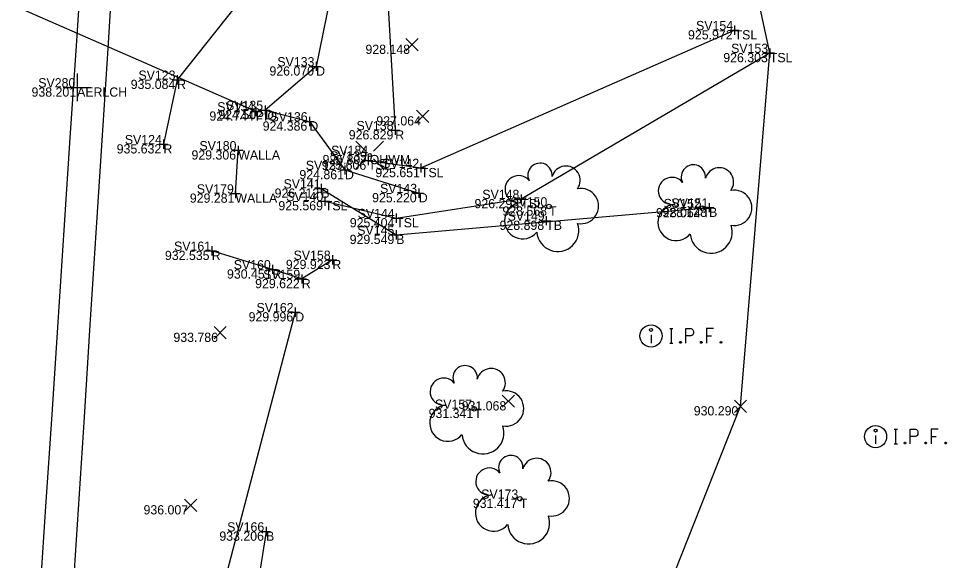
# Model space of a CAD drawing. Extents: x 1988835 to 1989144, y 657973 to 659339.
# Drawn here: x 1988993.8 to 1989094.4, y 658616.1 to 658674.7 of the extents above; entities that cross this region are included whole.
import ezdxf

# ---------------------------------------------------------------- set-up
doc = ezdxf.new("R2010")
doc.units = 0
for name, color, linetype in [('BR_X_SV_Abut', 7, 'Continuous'), ('BR_X_SV_Abut_Text', 7, 'Continuous'), ('DR_X_Culvert', 7, 'Continuous'), ('DR_X_Ditch', 7, 'Continuous'), ('DR_X_Elev_Flow', 7, 'Continuous'), ('DR_X_Erosion_Control', 7, 'Continuous'), ('DT_X_Terrain_Boundary', 7, 'Continuous'), ('PV_X_EOP', 7, 'Continuous'), ('PV_X_Shoulder_Aggregate', 7, 'Continuous'), ('SV_X_Break_Lines', 7, 'Continuous'), ('SV_X_Control_Cells_Found', 7, 'Continuous'), ('SV_X_LiDAR_Check_Spots', 7, 'Continuous'), ('SV_X_Mon_Cells_Found', 7, 'Continuous'), ('SV_X_Random_Point', 7, 'Continuous'), ('SV_X_Shot_Marker', 7, 'Continuous'), ('SV_X_Text_Comment', 7, 'Continuous'), ('SV_X_Toe_of_Slope', 7, 'Continuous'), ('SV_X_Top_of_Bank', 7, 'Continuous'), ('UT_X_Telecom', 7, 'Continuous'), ('UT_X_Telecom_Cells', 7, 'Continuous'), ('VG_X_Cells', 7, 'Continuous')]:
    doc.layers.add(name, color=color, linetype=linetype)

msp = doc.modelspace()

# ---------------------------------------------------------------- linework, layer by layer
at = {"layer": 'BR_X_SV_Abut'}
msp.add_lwpolyline([(1989017.3, 658655.79), (1989017.61, 658660.47)], dxfattribs=at)
at = {"layer": 'DR_X_Culvert'}
msp.add_line((1989019.51, 658664.68), (1988958.48, 658691.4), dxfattribs=at)
at = {"layer": 'DR_X_Ditch'}
for points in [[(1989027.55, 658676.83), (1989026.05, 658669.56), (1989020.51, 658664.83), (1989025.32, 658663.6), (1989029.18, 658658.34), (1989037.18, 658655.84)], [(1989023.79, 658642.94), (1989012.7, 658600.75), (1989009.34, 658575.2), (1989005.48, 658554.05)]]:
    msp.add_lwpolyline(points, dxfattribs=at)
at = {"layer": 'DR_X_Elev_Flow'}
for p, q in [((1989019.51, 658665.18), (1989019.51, 658664.18)), ((1989019.01, 658664.68), (1989020.01, 658664.68)), ((1989019.51, 658664.68), (1989019.51, 658664.68))]:
    msp.add_line(p, q, dxfattribs=at)
at = {"layer": 'DR_X_Erosion_Control'}
for points in [[(1989026.58, 658683.91), (1989017.28, 658675.99), (1989010.98, 658668.11), (1989009.49, 658661.13)], [(1989033.84, 658676.66), (1989034.63, 658662.65)], [(1989027.81, 658648.61), (1989024.5, 658646.54), (1989021.33, 658647.58), (1989014.73, 658649.59)]]:
    msp.add_lwpolyline(points, dxfattribs=at)
at = {"layer": 'DT_X_Terrain_Boundary'}
msp.add_lwpolyline([(1988964.62, 658494.73), (1988978, 658493.13), (1988991.98, 658491.88), (1988996.56, 658563.26), (1989005.48, 658554.05), (1989016.29, 658553.87), (1989055.69, 658591.48), (1989072.05, 658632.76), (1989075.24, 658671.01), (1989070.71, 658691.89), (1989069.57, 658706.91), (1989055.31, 658717.34), (1989045.38, 658731.75), (1989037.8, 658764.08), (1989044.5, 658795.25), (1989034.59, 658795.83), (1989024.05, 658796.33), (1989020.1, 658798.63), (1989011.65, 658798.86), (1989014.02, 658836.36)], dxfattribs=at)
at = {"layer": 'PV_X_EOP'}
msp.add_lwpolyline([(1988996.1, 658611.92), (1988996.76, 658621.89), (1988997.42, 658631.87), (1988998.08, 658641.85), (1988998.74, 658651.83), (1988999.4, 658661.81), (1989000.06, 658671.78), (1989000.73, 658681.76), (1989001.39, 658691.74), (1989002.05, 658701.72), (1989002.71, 658711.7), (1989003.37, 658721.68), (1989004.03, 658731.65), (1989004.69, 658741.63), (1989005.35, 658751.61), (1989006.01, 658761.59), (1989006.67, 658771.57), (1989007.33, 658781.54), (1989007.99, 658791.52), (1989008.65, 658801.5), (1989009.31, 658811.48), (1989009.97, 658821.46), (1989010.63, 658831.43), (1989011.29, 658841.41)], dxfattribs=at)
at = {"layer": 'PV_X_Shoulder_Aggregate'}
msp.add_lwpolyline([(1988999.65, 658611.63), (1989000.29, 658621.61), (1989000.93, 658631.59), (1989001.57, 658641.57), (1989002.21, 658651.55), (1989002.85, 658661.53), (1989003.49, 658671.51), (1989004.13, 658681.49), (1989004.77, 658691.47), (1989005.41, 658701.45), (1989006.05, 658711.43), (1989006.69, 658721.41), (1989007.33, 658731.39), (1989007.96, 658741.37), (1989008.6, 658751.35), (1989009.24, 658761.33), (1989009.88, 658771.31), (1989010.52, 658781.29), (1989011.16, 658791.27), (1989011.8, 658801.25), (1989012.44, 658811.22), (1989013.08, 658821.2), (1989013.72, 658831.18), (1989013.76, 658831.87)], dxfattribs=at)
at = {"layer": 'SV_X_Break_Lines'}
for points in [[(1989026.61, 658656.34), (1989034.73, 658651.32), (1989068.65, 658654.26)], [(1989020.62, 658619.19), (1989017.63, 658600.41), (1989016.29, 658553.87)]]:
    msp.add_lwpolyline(points, dxfattribs=at)
at = {"layer": 'SV_X_Control_Cells_Found'}
for p, q in [((1989030.35, 658661.47), (1989031.44, 658660.38)), ((1989032.27, 658660.38), (1989033.36, 658661.47)), ((1989030.35, 658658.45), (1989031.44, 658659.55)), ((1989032.27, 658659.55), (1989033.36, 658658.45))]:
    msp.add_line(p, q, dxfattribs=at)
msp.add_circle((1989031.86, 658659.97), 0.17, dxfattribs=at)
at = {"layer": 'SV_X_LiDAR_Check_Spots'}
for p, q in [((1989000.14, 658668.78), (1989000.14, 658665.78)), ((1988998.64, 658667.28), (1989001.64, 658667.28)), ((1989000.14, 658667.28), (1989000.14, 658667.28))]:
    msp.add_line(p, q, dxfattribs=at)
at = {"layer": 'SV_X_Mon_Cells_Found'}
for p, q in [((1989062.36, 658640.49), (1989062.36, 658639.6)), ((1989086.7, 658629.59), (1989086.7, 658628.7))]:
    msp.add_line(p, q, dxfattribs=at)
for points in [[(1989064.39, 658641.17), (1989064.74, 658641.17)], [(1989064.57, 658639.57), (1989064.57, 658641.17)], [(1989066.13, 658639.57), (1989066.13, 658641.17), (1989066.66, 658641.17), (1989066.72, 658641.16), (1989066.79, 658641.13), (1989066.83, 658641.11), (1989066.86, 658641.08), (1989066.9, 658641.02), (1989066.94, 658640.96), (1989066.96, 658640.86), (1989066.96, 658640.7), (1989066.95, 658640.65), (1989066.93, 658640.58), (1989066.88, 658640.49), (1989066.84, 658640.45), (1989066.8, 658640.43), (1989066.75, 658640.4), (1989066.66, 658640.39), (1989066.13, 658640.39)], [(1989069.14, 658641.17), (1989068.38, 658641.17), (1989068.38, 658639.57)], [(1989064.39, 658639.57), (1989064.74, 658639.57)], [(1989065.53, 658639.78), (1989065.58, 658639.78), (1989065.61, 658639.76), (1989065.65, 658639.71), (1989065.65, 658639.65), (1989065.61, 658639.6), (1989065.58, 658639.57), (1989065.53, 658639.57), (1989065.49, 658639.6), (1989065.46, 658639.65), (1989065.46, 658639.71), (1989065.49, 658639.76), (1989065.53, 658639.78)], [(1989067.77, 658639.78), (1989067.83, 658639.78), (1989067.86, 658639.76), (1989067.9, 658639.71), (1989067.9, 658639.65), (1989067.86, 658639.6), (1989067.83, 658639.57), (1989067.77, 658639.57), (1989067.74, 658639.6), (1989067.71, 658639.65), (1989067.71, 658639.71), (1989067.74, 658639.76), (1989067.77, 658639.78)], [(1989068.38, 658640.39), (1989068.92, 658640.39)], [(1989069.92, 658639.78), (1989069.98, 658639.78), (1989070.01, 658639.76), (1989070.05, 658639.71), (1989070.05, 658639.65), (1989070.01, 658639.6), (1989069.98, 658639.57), (1989069.92, 658639.57), (1989069.89, 658639.6), (1989069.86, 658639.65), (1989069.86, 658639.71), (1989069.89, 658639.76), (1989069.92, 658639.78)], [(1989088.73, 658630.27), (1989089.08, 658630.27)], [(1989088.91, 658628.67), (1989088.91, 658630.27)], [(1989090.47, 658628.67), (1989090.47, 658630.27), (1989091, 658630.27), (1989091.06, 658630.26), (1989091.13, 658630.23), (1989091.17, 658630.21), (1989091.2, 658630.18), (1989091.24, 658630.12), (1989091.28, 658630.06), (1989091.3, 658629.96), (1989091.3, 658629.8), (1989091.29, 658629.75), (1989091.27, 658629.68), (1989091.22, 658629.59), (1989091.18, 658629.55), (1989091.14, 658629.53), (1989091.09, 658629.5), (1989091, 658629.49), (1989090.47, 658629.49)], [(1989093.48, 658630.27), (1989092.72, 658630.27), (1989092.72, 658628.67)], [(1989088.73, 658628.67), (1989089.08, 658628.67)], [(1989089.87, 658628.88), (1989089.92, 658628.88), (1989089.95, 658628.86), (1989089.99, 658628.81), (1989089.99, 658628.75), (1989089.95, 658628.7), (1989089.92, 658628.67), (1989089.87, 658628.67), (1989089.83, 658628.7), (1989089.8, 658628.75), (1989089.8, 658628.81), (1989089.83, 658628.86), (1989089.87, 658628.88)], [(1989092.11, 658628.88), (1989092.17, 658628.88), (1989092.2, 658628.86), (1989092.24, 658628.81), (1989092.24, 658628.75), (1989092.2, 658628.7), (1989092.17, 658628.67), (1989092.11, 658628.67), (1989092.08, 658628.7), (1989092.05, 658628.75), (1989092.05, 658628.81), (1989092.08, 658628.86), (1989092.11, 658628.88)], [(1989092.72, 658629.49), (1989093.26, 658629.49)], [(1989094.26, 658628.88), (1989094.32, 658628.88), (1989094.35, 658628.86), (1989094.39, 658628.81), (1989094.39, 658628.75), (1989094.35, 658628.7), (1989094.32, 658628.67), (1989094.26, 658628.67), (1989094.23, 658628.7), (1989094.2, 658628.75), (1989094.2, 658628.81), (1989094.23, 658628.86), (1989094.26, 658628.88)]]:
    msp.add_lwpolyline(points, dxfattribs=at)
for centre, radius in [((1989062.36, 658640.37), 1.2), ((1989062.36, 658641.02), 0.16), ((1989086.7, 658629.47), 1.2), ((1989086.7, 658630.12), 0.16)]:
    msp.add_circle(centre, radius, dxfattribs=at)
at = {"layer": 'SV_X_Random_Point'}
for p, q in [((1989035.79, 658671.24), (1989037.12, 658672.58)), ((1989035.79, 658672.58), (1989037.12, 658671.24)), ((1989036.94, 658663.49), (1989038.27, 658664.83)), ((1989036.94, 658664.83), (1989038.27, 658663.49)), ((1989014.98, 658640.05), (1989016.31, 658641.39)), ((1989014.98, 658641.39), (1989016.31, 658640.05)), ((1989046.22, 658632.64), (1989047.56, 658633.97)), ((1989046.22, 658633.97), (1989047.56, 658632.64)), ((1989071.39, 658632.09), (1989072.72, 658633.43)), ((1989071.39, 658633.43), (1989072.72, 658632.09)), ((1989011.78, 658621.37), (1989013.11, 658622.71)), ((1989011.78, 658622.71), (1989013.11, 658621.37))]:
    msp.add_line(p, q, dxfattribs=at)
at = {"layer": 'SV_X_Shot_Marker'}
for p, q in [((1989071.42, 658673.98), (1989071.42, 658672.98)), ((1989070.92, 658673.48), (1989071.92, 658673.48)), ((1989071.42, 658673.48), (1989071.42, 658673.48)), ((1989074.74, 658671.01), (1989075.74, 658671.01)), ((1989075.24, 658671.51), (1989075.24, 658670.51)), ((1989075.24, 658671.01), (1989075.24, 658671.01)), ((1989026.05, 658670.06), (1989026.05, 658669.06)), ((1989025.55, 658669.56), (1989026.55, 658669.56)), ((1989026.05, 658669.56), (1989026.05, 658669.56)), ((1989010.48, 658668.11), (1989011.48, 658668.11)), ((1989010.98, 658668.61), (1989010.98, 658667.61)), ((1989010.98, 658668.11), (1989010.98, 658668.11)), ((1989020.01, 658664.83), (1989021.01, 658664.83)), ((1989020.51, 658665.33), (1989020.51, 658664.33)), ((1989020.51, 658664.83), (1989020.51, 658664.83)), ((1989025.32, 658664.1), (1989025.32, 658663.1)), ((1989024.82, 658663.6), (1989025.82, 658663.6)), ((1989025.32, 658663.6), (1989025.32, 658663.6)), ((1989034.63, 658663.15), (1989034.63, 658662.15)), ((1989034.13, 658662.65), (1989035.13, 658662.65)), ((1989034.63, 658662.65), (1989034.63, 658662.65)), ((1989008.99, 658661.13), (1989009.99, 658661.13)), ((1989009.49, 658661.63), (1989009.49, 658660.63)), ((1989009.49, 658661.13), (1989009.49, 658661.13)), ((1989017.61, 658660.97), (1989017.61, 658659.97)), ((1989017.11, 658660.47), (1989018.11, 658660.47)), ((1989017.61, 658660.47), (1989017.61, 658660.47)), ((1989031.71, 658659.86), (1989031.71, 658658.86)), ((1989029.18, 658658.84), (1989029.18, 658657.84)), ((1989031.21, 658659.36), (1989032.21, 658659.36)), ((1989031.71, 658659.36), (1989031.71, 658659.36)), ((1989037.41, 658659.06), (1989037.41, 658658.06)), ((1989028.68, 658658.34), (1989029.68, 658658.34)), ((1989029.18, 658658.34), (1989029.18, 658658.34)), ((1989036.91, 658658.56), (1989037.91, 658658.56)), ((1989037.41, 658658.56), (1989037.41, 658658.56)), ((1989026.61, 658656.84), (1989026.61, 658655.84)), ((1989016.8, 658655.79), (1989017.8, 658655.79)), ((1989017.3, 658656.29), (1989017.3, 658655.29)), ((1989017.3, 658655.79), (1989017.3, 658655.79)), ((1989026.11, 658656.34), (1989027.11, 658656.34)), ((1989026.61, 658656.34), (1989026.61, 658656.34)), ((1989036.68, 658655.84), (1989037.68, 658655.84)), ((1989037.18, 658656.34), (1989037.18, 658655.34)), ((1989037.18, 658655.84), (1989037.18, 658655.84)), ((1989048.27, 658655.7), (1989048.27, 658654.7)), ((1989026.5, 658654.97), (1989027.5, 658654.97)), ((1989027, 658655.47), (1989027, 658654.47)), ((1989027, 658654.97), (1989027, 658654.97)), ((1989047.77, 658655.2), (1989048.77, 658655.2)), ((1989048.27, 658655.2), (1989048.27, 658655.2)), ((1989068.65, 658654.76), (1989068.65, 658653.76)), ((1989068.15, 658654.26), (1989069.15, 658654.26)), ((1989068.65, 658654.26), (1989068.65, 658654.26)), ((1989034.23, 658653.13), (1989035.23, 658653.13)), ((1989034.73, 658653.63), (1989034.73, 658652.63)), ((1989034.73, 658653.13), (1989034.73, 658653.13)), ((1989050.5, 658652.85), (1989051.5, 658652.85)), ((1989051, 658653.35), (1989051, 658652.35)), ((1989051, 658652.85), (1989051, 658652.85)), ((1989034.73, 658651.82), (1989034.73, 658650.82)), ((1989034.23, 658651.32), (1989035.23, 658651.32)), ((1989034.73, 658651.32), (1989034.73, 658651.32)), ((1989014.73, 658650.09), (1989014.73, 658649.09)), ((1989014.23, 658649.59), (1989015.23, 658649.59)), ((1989014.73, 658649.59), (1989014.73, 658649.59)), ((1989027.81, 658649.11), (1989027.81, 658648.11)), ((1989021.33, 658648.08), (1989021.33, 658647.08)), ((1989027.31, 658648.61), (1989028.31, 658648.61)), ((1989027.81, 658648.61), (1989027.81, 658648.61)), ((1989020.83, 658647.58), (1989021.83, 658647.58)), ((1989021.33, 658647.58), (1989021.33, 658647.58)), ((1989024.5, 658647.04), (1989024.5, 658646.04)), ((1989024, 658646.54), (1989025, 658646.54)), ((1989024.5, 658646.54), (1989024.5, 658646.54)), ((1989023.29, 658642.94), (1989024.29, 658642.94)), ((1989023.79, 658643.44), (1989023.79, 658642.44)), ((1989023.79, 658642.94), (1989023.79, 658642.94)), ((1989020.62, 658619.69), (1989020.62, 658618.69)), ((1989020.12, 658619.19), (1989021.12, 658619.19)), ((1989020.62, 658619.19), (1989020.62, 658619.19))]:
    msp.add_line(p, q, dxfattribs=at)
at = {"layer": 'SV_X_Toe_of_Slope'}
for points in [[(1989031.71, 658659.36), (1989037.41, 658658.56), (1989071.42, 658673.48)], [(1989027, 658654.97), (1989034.73, 658653.13), (1989048.27, 658655.2), (1989075.24, 658671.01)]]:
    msp.add_lwpolyline(points, dxfattribs=at)
at = {"layer": 'SV_X_Top_of_Bank'}
msp.add_lwpolyline([(1989051, 658652.85), (1989051, 658652.85)], dxfattribs=at)
at = {"layer": 'VG_X_Cells'}
for centre in [(1989051.3, 658654.39), (1989067.93, 658654.21), (1989043.19, 658632.48), (1989048.14, 658622.74)]:
    msp.add_circle(centre, 0.24, dxfattribs=at)
for centre, radius, start, end in [((1989050.32, 658657.76), 1.32, 354.0047, 205.9741), ((1989053.13, 658657.22), 1.55, 323.83, 165.0376), ((1989066.95, 658657.58), 1.32, 354.0047, 205.9741), ((1989048, 658656.26), 1.47, 39.0625, 279.5412), ((1989069.76, 658657.04), 1.55, 323.83, 165.0376), ((1989064.62, 658656.07), 1.47, 39.0625, 279.5412), ((1989054.76, 658654.43), 1.91, 259.1453, 101.4596), ((1989071.39, 658654.24), 1.91, 259.1453, 101.4596), ((1989048.45, 658652.85), 1.97, 96.1722, 320.5737), ((1989065.08, 658652.66), 1.97, 96.1722, 320.5737), ((1989052.25, 658651.79), 2.28, 184.9476, 19.4572), ((1989068.88, 658651.6), 2.28, 184.9476, 19.4572), ((1989042.21, 658635.84), 1.32, 354.0047, 205.9741), ((1989045.02, 658635.3), 1.55, 323.83, 165.0376), ((1989039.88, 658634.34), 1.47, 39.0625, 279.5412), ((1989046.65, 658632.51), 1.91, 259.1453, 101.4596), ((1989040.34, 658630.93), 1.97, 96.1722, 320.5737), ((1989044.14, 658629.87), 2.28, 184.9476, 19.4572), ((1989047.16, 658626.11), 1.32, 354.0047, 205.9741), ((1989049.97, 658625.57), 1.55, 323.83, 165.0376), ((1989044.83, 658624.6), 1.47, 39.0625, 279.5412), ((1989051.6, 658622.77), 1.91, 259.1453, 101.4596), ((1989045.29, 658621.19), 1.97, 96.1722, 320.5737), ((1989049.09, 658620.13), 2.28, 184.9476, 19.4572)]:
    msp.add_arc(centre, radius, start, end, dxfattribs=at)

# ---------------------------------------------------------------- texts
at = {"layer": 'BR_X_SV_Abut_Text'}
for s, p in [('SV180', (1989013.4, 658660.47)), ('929.306', (1989012.54, 658659.47)), ('WALLA', (1989017.61, 658659.47)), ('SV179', (1989013.12, 658655.79)), ('929.281', (1989012.36, 658654.79)), ('WALLA', (1989017.3, 658654.79))]:
    msp.add_text(s, height=1, dxfattribs=at).set_placement(p)
at = {"layer": 'SV_X_Text_Comment'}
for s, p in [('SV154', (1989067.24, 658673.48)), ('SV153', (1989071.04, 658671.01)), ('SV133', (1989021.85, 658669.56)), ('SV123', (1989006.79, 658668.11)), ('SV280', (1988995.93, 658667.28)), ('SV135', (1989016.29, 658664.83)), ('SV134', (1989015.33, 658664.68)), ('SV136', (1989021.11, 658663.6)), ('SV138', (1989030.43, 658662.65)), ('SV124', (1989005.31, 658661.13)), ('SV184', (1989027.68, 658659.97)), ('SV139', (1989027.53, 658659.36)), ('SV137', (1989024.93, 658658.34)), ('SV142', (1989033.21, 658658.56)), ('SV141', (1989022.52, 658656.34)), ('SV143', (1989032.98, 658655.84)), ('SV140', (1989022.8, 658654.97)), ('SV148', (1989044.07, 658655.2)), ('SV150', (1989047.1, 658654.39)), ('SV152', (1989063.73, 658654.21)), ('SV151', (1989064.56, 658654.26)), ('SV144', (1989030.55, 658653.13)), ('SV149', (1989046.81, 658652.85)), ('SV145', (1989030.51, 658651.32)), ('SV161', (1989010.65, 658649.59)), ('SV158', (1989023.61, 658648.61)), ('SV160', (1989017.12, 658647.58)), ('SV159', (1989020.31, 658646.54)), ('SV162', (1989019.59, 658642.94)), ('SV157', (1989038.94, 658632.48)), ('SV173', (1989043.95, 658622.74)), ('SV166', (1989016.41, 658619.19))]:
    msp.add_text(s, height=1, dxfattribs=at).set_placement(p)
at = {"layer": 'UT_X_Telecom'}
for s, p in [('TSL', (1989071.42, 658672.48)), ('TSL', (1989075.24, 658670.01)), ('D', (1989026.05, 658668.56)), ('R', (1989010.98, 658667.11)), ('AERLCH', (1989000.14, 658666.28)), ('D', (1989020.51, 658663.83)), ('PIO', (1989019.51, 658663.68)), ('D', (1989025.32, 658662.6)), ('R', (1989034.63, 658661.65)), ('R', (1989009.49, 658660.13)), ('OHWM', (1989031.86, 658658.97)), ('TSL', (1989031.71, 658658.36)), ('D', (1989029.18, 658657.34)), ('TSL', (1989037.41, 658657.56)), ('B', (1989026.61, 658655.34)), ('D', (1989037.18, 658654.84)), ('TSL', (1989027, 658653.97)), ('TSL', (1989048.27, 658654.2)), ('T', (1989051.3, 658653.39)), ('T', (1989067.93, 658653.21)), ('B', (1989068.65, 658653.26)), ('TSL', (1989034.73, 658652.13)), ('TB', (1989051, 658651.85)), ('B', (1989034.73, 658650.32)), ('R', (1989014.73, 658648.59)), ('R', (1989027.81, 658647.61)), ('R', (1989021.33, 658646.58)), ('R', (1989024.5, 658645.54)), ('D', (1989023.79, 658641.94)), ('T', (1989043.19, 658631.48)), ('T', (1989048.14, 658621.74)), ('B', (1989020.62, 658618.19))]:
    msp.add_text(s, height=1, dxfattribs=at).set_placement(p)
at = {"layer": 'UT_X_Telecom_Cells'}
for s, p in [('925.972', (1989066.37, 658672.48)), ('928.148', (1989031.4, 658670.91)), ('926.303', (1989070.19, 658670.01)), ('926.070', (1989020.99, 658668.56)), ('935.084', (1989005.95, 658667.11)), ('938.201', (1988995.2, 658666.28)), ('924.502', (1989015.45, 658663.83)), ('924.744', (1989014.48, 658663.68)), ('927.064', (1989032.58, 658663.16)), ('924.386', (1989020.26, 658662.6)), ('926.829', (1989029.59, 658661.65)), ('935.632', (1989004.43, 658660.13)), ('925.807', (1989026.75, 658658.97)), ('925.606', (1989026.65, 658658.36)), ('924.861', (1989024.24, 658657.34)), ('925.651', (1989032.47, 658657.56)), ('926.212', (1989021.55, 658655.34)), ('925.220', (1989032.12, 658654.84)), ('925.569', (1989021.96, 658653.97)), ('926.293', (1989043.22, 658654.2)), ('928.568', (1989046.25, 658653.39)), ('928.064', (1989062.9, 658653.21)), ('928.128', (1989063.59, 658653.26)), ('925.404', (1989029.7, 658652.13)), ('928.898', (1989045.94, 658651.85)), ('929.549', (1989029.69, 658650.32)), ('932.535', (1989009.66, 658648.59)), ('929.923', (1989022.77, 658647.61)), ('930.451', (1989016.39, 658646.58)), ('929.622', (1989019.44, 658645.54)), ('929.996', (1989018.73, 658641.94)), ('933.786', (1989010.58, 658639.72)), ('931.068', (1989041.83, 658632.3)), ('930.290', (1989066.99, 658631.76)), ('931.341', (1989038.25, 658631.48)), ('931.417', (1989043.04, 658621.74)), ('936.007', (1989007.34, 658621.04)), ('933.206', (1989015.56, 658618.19))]:
    msp.add_text(s, height=1, dxfattribs=at).set_placement(p)

doc.saveas('drawing.dxf')
